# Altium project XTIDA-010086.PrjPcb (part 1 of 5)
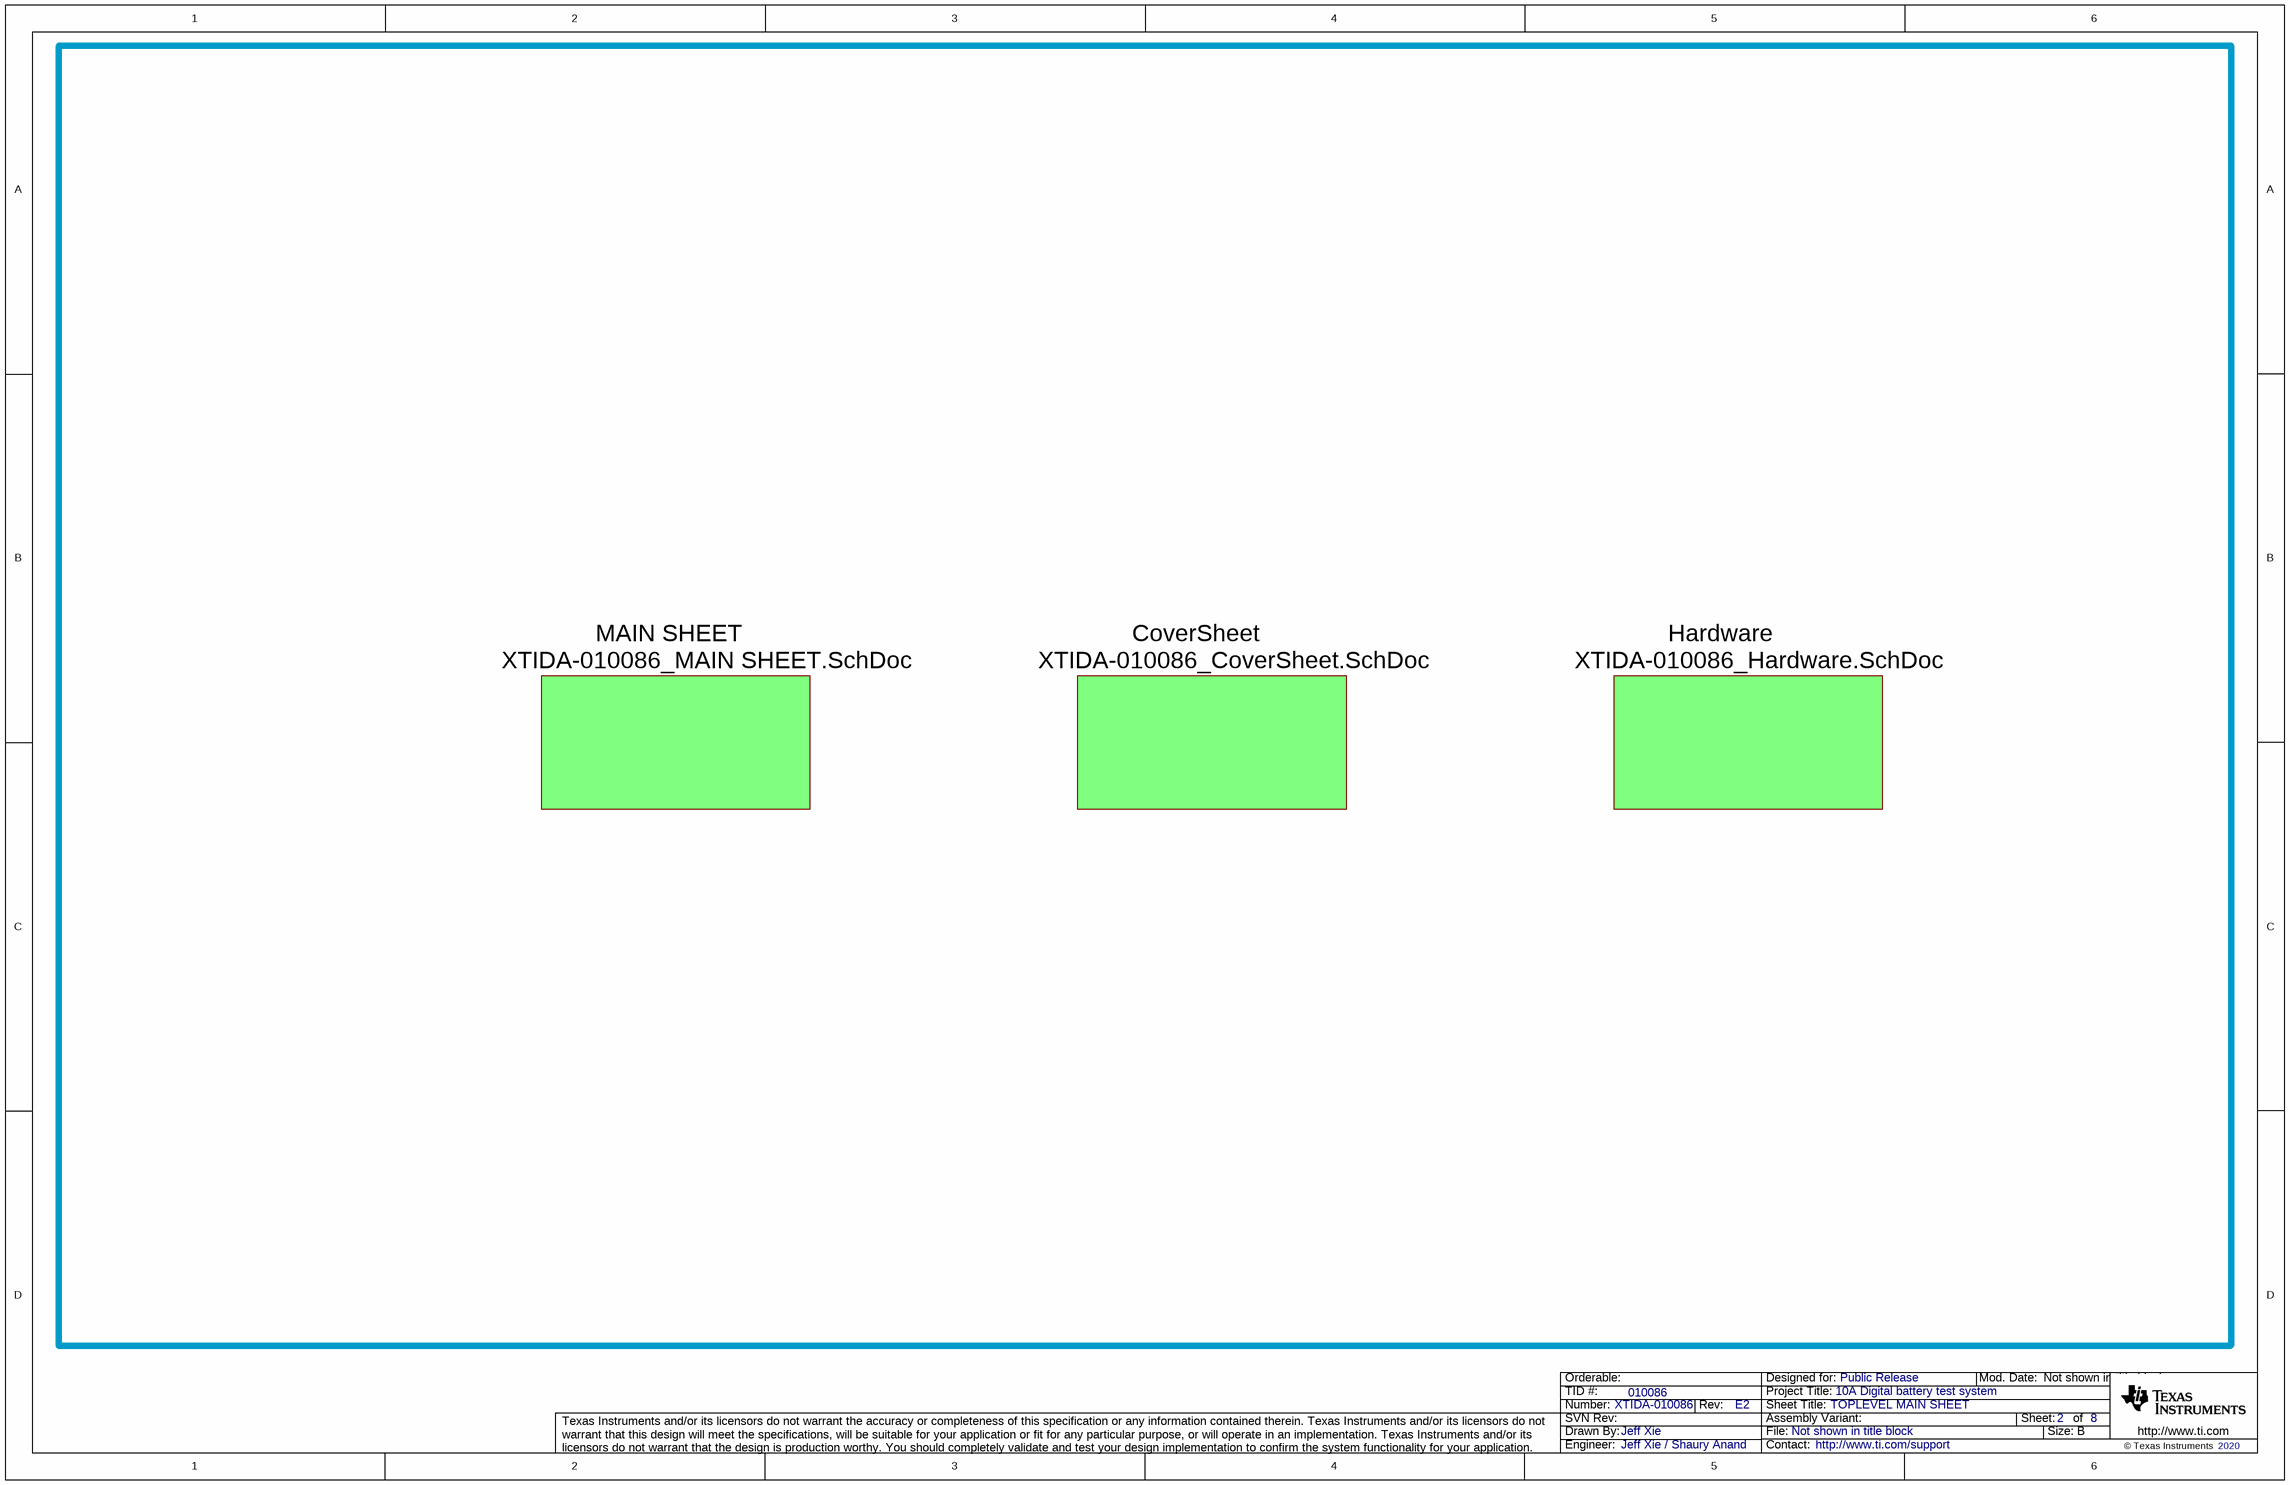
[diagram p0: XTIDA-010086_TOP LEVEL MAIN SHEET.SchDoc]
CopyrightYear: 2020; PCB_Layout: Avinash N; PCB_Rev: E2; PRJ_Customer: Public Release; PRJ_Engineer: Jeff Xie / Shaury Anand; PRJ_Number: XTIDA-010086; PRJ_Title: 10A Digital battery test system; SCH_Rev: E2; TechSupport: http://www.ti.com/support; TID: 010086
8 sheets, 1934 parts. Net scope: flat (ports and power ports of the same name join across sheets).
Board file: XTIDA-010086.PcbDoc
Sheets:
  XTIDA-010086_TOP LEVEL MAIN SHEET.SchDoc
    MAIN SHEET = XTIDA-010086_MAIN SHEET.SchDoc
      Ch1 = XTIDA-010086_Power Stage.SchDoc
      Ch2 = XTIDA-010086_Power Stage.SchDoc
      Ch3 = XTIDA-010086_Power Stage.SchDoc
      Ch4 = XTIDA-010086_Power Stage.SchDoc
      Ch5 = XTIDA-010086_Power Stage.SchDoc
      Ch6 = XTIDA-010086_Power Stage.SchDoc
      Ch7 = XTIDA-010086_Power Stage.SchDoc
      Ch8 = XTIDA-010086_Power Stage.SchDoc
      ADC = XTIDA-010086_ADC.SchDoc
      Bias Power Supply = XTIDA-010086_Bias Power Supply.SchDoc
      Control Card_28379 = XTIDA-010086_Control Card_28379.SchDoc
    CoverSheet = XTIDA-010086_CoverSheet.SchDoc
    Hardware = XTIDA-010086_Hardware.SchDoc

## Sheet XTIDA-010086_TOP LEVEL MAIN SHEET.SchDoc: TOPLEVEL MAIN SHEET
size 431 x 279 mm; Date: Not shown in title block; ApprovedBy: Not shown in title block; CheckedBy: Not shown in title block; Author: Not shown in title block; CompanyName: Not shown in title block; DrawnBy: Jeff Xie; Engineer: Not shown in title block; Organization: Not shown in title block; Address1: Not shown in title block; Address2: Not shown in title block; Address3: Not shown in title block; Address4: Not shown in title block; DocumentNumber: 1; Revision: Use project parameter SCH_Rev; SheetNumber: 2; SheetTotal: 8; PageSetup: Record=PageOptions¦CenterHorizontal=True¦CenterVertical=True¦PrintScale=1.00¦XCorrection=1.00¦YCorrection=1.00¦PrintKind=0¦BorderSize=5000000¦LeftOffset=0¦BottomOffset=0¦Orientation=2¦PaperLength=1000¦PaperWidth=1000¦Scale=100¦PaperSource=15¦PrintQuality=600¦MediaType=1¦DitherType=10¦PaperKind=Letter¦PrintScaleMode=1

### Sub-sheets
CoverSheet = XTIDA-010086_CoverSheet.SchDoc: no entries
Hardware = XTIDA-010086_Hardware.SchDoc: no entries
MAIN SHEET = XTIDA-010086_MAIN SHEET.SchDoc: no entries

## Sheet XTIDA-010086_MAIN SHEET.SchDoc: MAIN-Sheet
size 558 x 431 mm; Date: Not shown in title block; ApprovedBy: Not shown in title block; CheckedBy: Not shown in title block; Author: Not shown in title block; CompanyName: Not shown in title block; DrawnBy: Jeff Xie; Engineer: Not shown in title block; Organization: Not shown in title block; Address1: Not shown in title block; Address2: Not shown in title block; Address3: Not shown in title block; Address4: Not shown in title block; DocumentNumber: 1; Revision: Use project parameter SCH_Rev; SheetNumber: 3; SheetTotal: 8; PageSetup: Record=PageOptions¦CenterHorizontal=True¦CenterVertical=True¦PrintScale=1.00¦XCorrection=1.00¦YCorrection=1.00¦PrintKind=0¦BorderSize=5000000¦LeftOffset=0¦BottomOffset=0¦Orientation=2¦PaperLength=1000¦PaperWidth=1000¦Scale=100¦PaperSource=15¦PrintQuality=600¦MediaType=1¦DitherType=10¦PaperKind=Letter¦PrintScaleMode=1
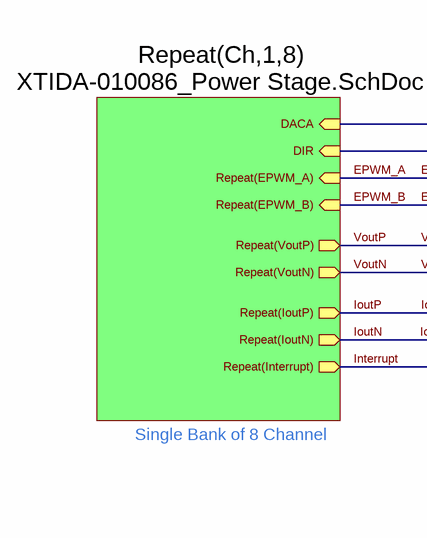
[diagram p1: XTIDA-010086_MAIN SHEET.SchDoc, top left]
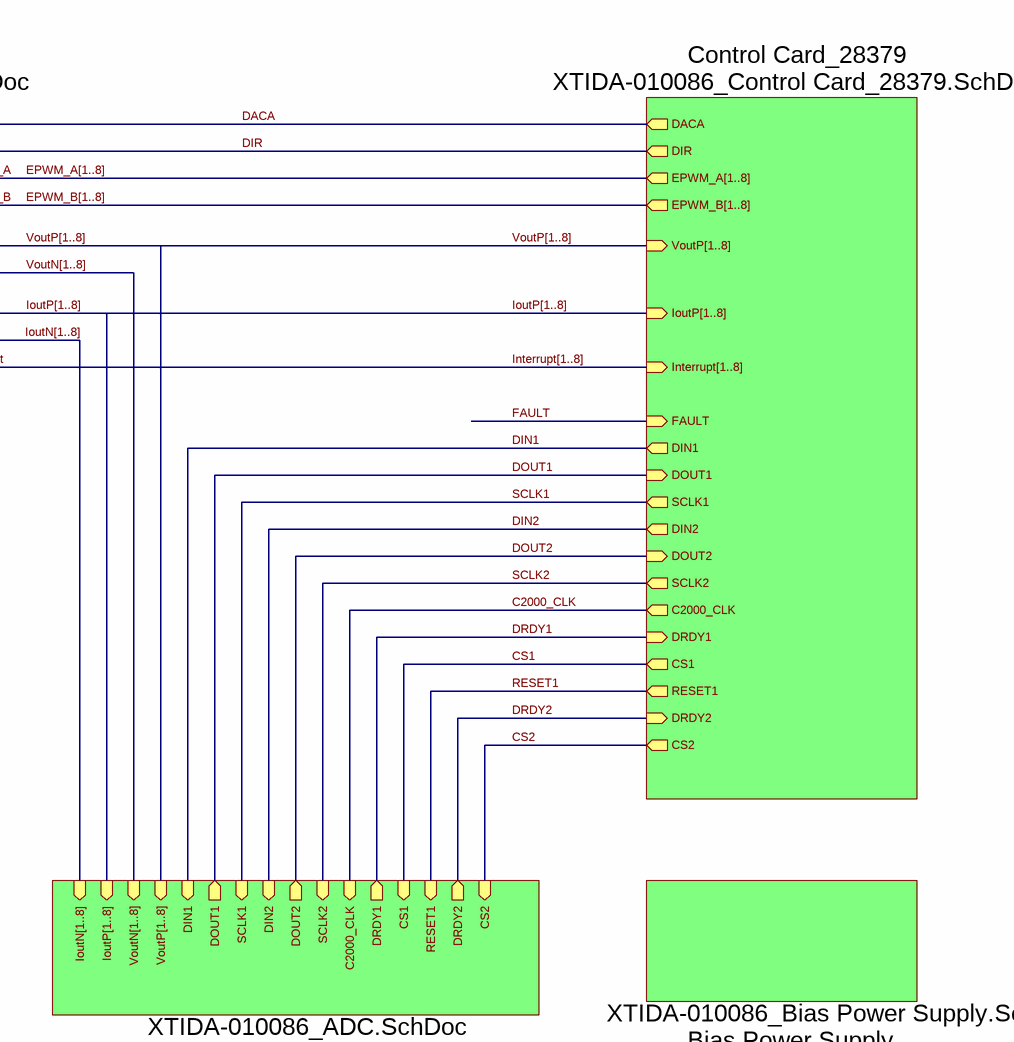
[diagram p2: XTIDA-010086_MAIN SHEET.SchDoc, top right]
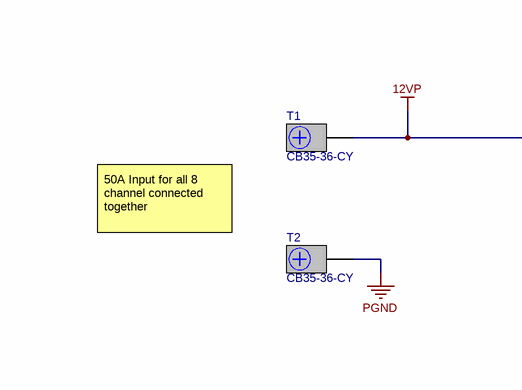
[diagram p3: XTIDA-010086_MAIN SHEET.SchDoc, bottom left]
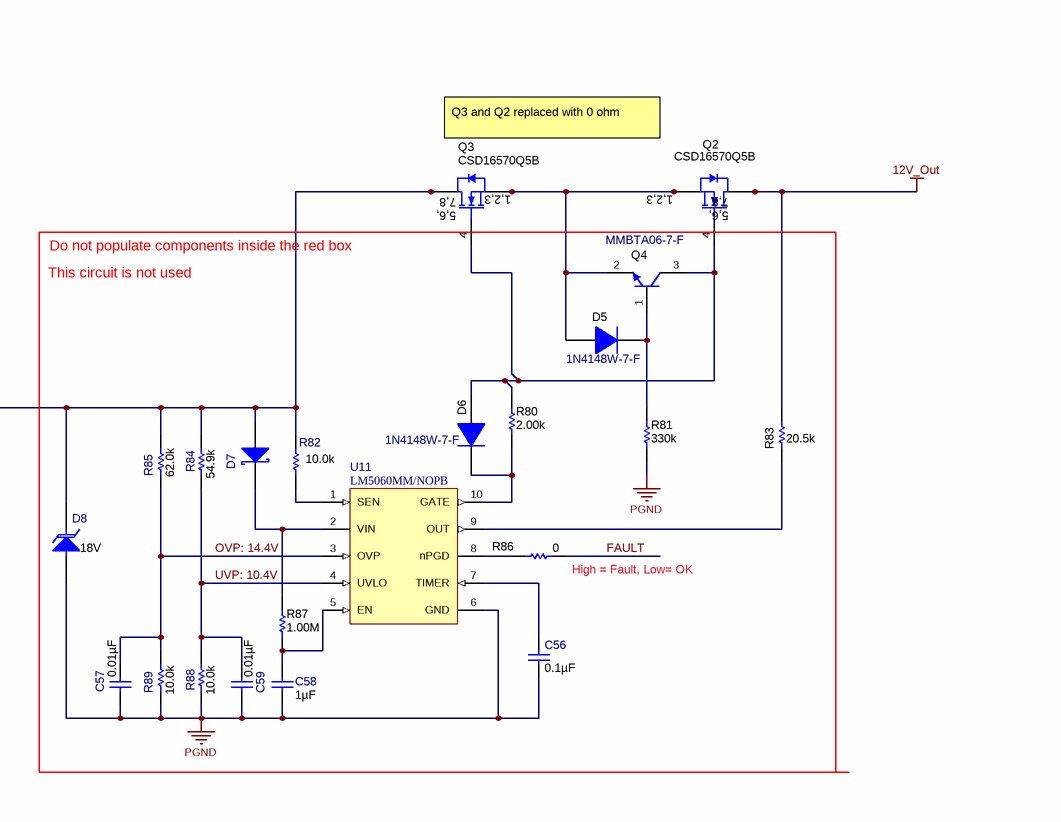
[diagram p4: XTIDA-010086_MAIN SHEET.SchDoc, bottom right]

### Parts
C56  ValueDisplayed: 0.1µF  [0603L]  (hidden comment: C0603C104J3RACTU)
C57  ValueDisplayed: 0.01µF  [0603L]  (hidden comment: GRM1885C1H103JA01D)
C58  ValueDisplayed: 1µF  [0603L]  (hidden comment: C0603C105K3RACTU)
C59  ValueDisplayed: 0.01µF  [0603L]  (hidden comment: GRM1885C1H103JA01D)
D5  1N4148W-7-F  [SOD-123]
D6  1N4148W-7-F  [SOD-123]
D7  NSR0240V2T1G  [SOD-523]  (value not drawn)
D8  value 18V  [SMA]  (hidden comment: SMAJ18A)
Q2  CSD16570Q5B  [DNK0008A]
Q3  CSD16570Q5B  [DNK0008A]
Q4  MMBTA06-7-F  [SOT-23]
R80  ValueDisplayed: 2.00k  [0603]  (hidden comment: CRCW06032K00FKEA)
R81  ValueDisplayed: 330k  [0603]  (hidden comment: RC0603FR-07330KL)
R82  ValueDisplayed: 10.0k  [0603L]  (hidden comment: RC0603FR-0710KL)
R83  ValueDisplayed: 20.5k  [0603]  (hidden comment: CRCW060320K5FKEA)
R84  ValueDisplayed: 54.9k  [0603L]  (hidden comment: RC0603FR-0754K9L)
R85  ValueDisplayed: 62.0k  [0603L]  (hidden comment: RC0603FR-0762KL)
R86  ValueDisplayed: 0  [0402]  (hidden comment: CRCW04020000Z0ED)
R87  ValueDisplayed: 1.00M  [0603]  (hidden comment: CRCW06031M00FKEA)
R88  ValueDisplayed: 10.0k  [0603L]  (hidden comment: RC0603FR-0710KL)
R89  ValueDisplayed: 10.0k  [0603L]  (hidden comment: RC0603FR-0710KL)
T1  CB35-36-CY  [CB35-36-CY]
T2  CB35-36-CY  [CB35-36-CY]
U11  LM5060MM/NOPB  [MUB10A_N]

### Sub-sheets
ADC = XTIDA-010086_ADC.SchDoc: VoutP[1..8] (in), IoutN[1..8] (in), IoutP[1..8] (in), VoutN[1..8] (in), DIN1 (in), DOUT1 (out), SCLK1 (in), DRDY1 (out), CS1 (in), RESET1 (in), SCLK2 (in), DIN2 (in), DOUT2 (out), DRDY2 (out), CS2 (in), C2000_CLK (in)
Bias Power Supply = XTIDA-010086_Bias Power Supply.SchDoc: no entries
Control Card_28379 = XTIDA-010086_Control Card_28379.SchDoc: SCLK1 (out), VoutP[1..8] (in), EPWM_A[1..8] (out), EPWM_B[1..8] (out), IoutP[1..8] (in), DIN2 (out), SCLK2 (out), DIN1 (out), DOUT1 (in), DOUT2 (in), C2000_CLK (out), DRDY1 (in), RESET1 (out), CS1 (out), DRDY2 (in), CS2 (out), FAULT (in), Interrupt[1..8] (in), DACA (out), DIR (out)
Repeat(Ch,1,8) = XTIDA-010086_Power Stage.SchDoc: Repeat(VoutP) (out), Repeat(IoutP) (out), Repeat(EPWM_A) (in), Repeat(EPWM_B) (in), Repeat(VoutN) (out), Repeat(IoutN) (out), DIR (in), Repeat(Interrupt) (out), DACA (in)

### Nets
12V_Out: Q2.5(D) Q2.6(D) Q2.7(D) Q2.8(D) Q2.9(D) R83.2
12VP: D7.2(A) D8.1(K) Q3.5(D) Q3.6(D) Q3.7(D) Q3.8(D) Q3.9(D) R82.1 R84.2 R85.2 T1.1
PGND: C56.1 C57.1 C58.2 C59.1 D8.2(A) R81.1 R88.1 R89.1 T2.1 U11.6(GND)
C2000_CLK: sheet ADC/C2000_CLK, sheet Control Card_28379/C2000_CLK
CS1: sheet ADC/CS1, sheet Control Card_28379/CS1
CS2: sheet ADC/CS2, sheet Control Card_28379/CS2
DACA: sheet Repeat(Ch,1,8)/DACA, sheet Control Card_28379/DACA
DIN1: sheet ADC/DIN1, sheet Control Card_28379/DIN1
DIN2: sheet ADC/DIN2, sheet Control Card_28379/DIN2
DIR: sheet Repeat(Ch,1,8)/DIR, sheet Control Card_28379/DIR
DOUT1: sheet ADC/DOUT1, sheet Control Card_28379/DOUT1
DOUT2: sheet ADC/DOUT2, sheet Control Card_28379/DOUT2
DRDY1: sheet ADC/DRDY1, sheet Control Card_28379/DRDY1
DRDY2: sheet ADC/DRDY2, sheet Control Card_28379/DRDY2
FAULT: R86.2 ; sheet Control Card_28379/FAULT
OVP: 14.4V: C57.2 R85.1 R89.2 U11.3(OVP)
RESET1: sheet ADC/RESET1, sheet Control Card_28379/RESET1
SCLK1: sheet ADC/SCLK1, sheet Control Card_28379/SCLK1
SCLK2: sheet ADC/SCLK2, sheet Control Card_28379/SCLK2
UVP: 10.4V: C59.2 R84.1 R88.2 U11.4(UVLO)
NetC56_2: C56.2 U11.7(TIMER)
NetC58_1: C58.1 R87.1 U11.5(EN)
NetD5_1: D5.1(K) Q4.1(B) R81.2
NetD5_2: D5.2(A) Q2.1(S) Q2.2(S) Q2.3(S) Q3.1(S) Q3.2(S) Q3.3(S) Q4.2(E)
NetD6_1: D6.1(K) R80.1 U11.10(GATE)
NetD6_2: D6.2(A) Q2.4(G) Q3.4(G) Q4.3(C) R80.2
NetD7_1: D7.1(K) R87.2 U11.2(VIN)
NetR82_2: R82.2 U11.1(SEN)
NetR83_1: R83.1 U11.9(OUT)
NetR86_1: R86.1 U11.8(nPGD)

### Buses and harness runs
bus EPWM_A[1..8] = sheet Control Card_28379/EPWM_A[1..8]
bus EPWM_B[1..8] = sheet Control Card_28379/EPWM_B[1..8]
bus Interrupt[1..8] = sheet Control Card_28379/Interrupt[1..8]
bus IoutN[1..8] = sheet ADC/IoutN[1..8]
bus IoutP[1..8] = sheet ADC/IoutP[1..8] = sheet Control Card_28379/IoutP[1..8]
bus VoutN[1..8] = sheet ADC/VoutN[1..8]
bus VoutP[1..8] = sheet ADC/VoutP[1..8] = sheet Control Card_28379/VoutP[1..8]

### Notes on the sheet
- Single Bank of 8 Channel
- Q3 and Q2 replaced with 0 ohm
- This circuit is not used
- Do not populate components inside the red box
- 50A Input for all 8 channel connected together
- (near R86) High = Fault, Low= OK

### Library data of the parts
C56 = C0603C104J3RACTU: CAP, CERM, 0.1 µF, 25 V, +/- 5%, X7R, 0603; Manufacturer: Kemet; Polarized: N; CompType: Capacitor; Value: 0.1uF; U/M: EA; Cap_F: 0.0000001; Tolerance_%: 5; Value1: Unknown; VDC_V: 25; Value2: 25V; TaMin_C: -55; TaMax_C: 125; Cap_Case: 0603; SizeArea_mm2: 1.28; SizeAreaWB_mm2: 4.68; SizeX_mm: 1.6; SizeY_mm: 0.8; SizeZ_mm: 1; AEC Category: Q200
C57 C59 = GRM1885C1H103JA01D: CAP, CERM, 0.01 µF, 50 V, +/- 5%, C0G/NP0, 0603; Manufacturer: MuRata; Polarized: N; CompType: Capacitor; Value: 0.01uF; U/M: EA; Cap_F: 0.00000001; Tolerance_%: 5; Value1: Unknown; VDC_V: 50; Value2: 50V; TaMin_C: -55; TaMax_C: 125; Cap_Case: 0603; SizeArea_mm2: 1.28; SizeAreaWB_mm2: 4.68; SizeX_mm: 1.6; SizeY_mm: 0.8; SizeZ_mm: 1; AEC Category: Q200
C58 = C0603C105K3RACTU: CAP, CERM, 1 µF, 25 V, +/- 10%, X7R, 0603; Manufacturer: Kemet; Polarized: N; CompType: Capacitor; Value: 1uF; U/M: EA; Cap_F: 0.000001; Tolerance_%: 10; Value1: Unknown; VDC_V: 25; Value2: 25V; TaMin_C: -55; TaMax_C: 125; Cap_Case: 0603; SizeArea_mm2: 1.28; SizeAreaWB_mm2: 4.68; SizeX_mm: 1.6; SizeY_mm: 0.8; SizeZ_mm: 1; AEC Category: Q200
D5 D6 = CMP-0029001-1: Diode, Ultrafast, 100 V, 0.15 A, SOD-123; Manufacturer: Diodes Inc.; Io_A: 150mA; Green_Lifecycle: Active; SizeAreaWB_mm2: 13.095; Vr_V: 100V; Green_REACh: Passed; Value1: 0.15A; TJmax_C: 150°C; U/M: EA; Value: 100V; SizeZ_mm: 1.35; SizeX_mm: 3.85; SizeY_mm: 1.7; Vf_V: 1.25V; SizeArea_mm2: 6.545; AEC Category: Q101
D7 = NSR0240V2T1G: Diode, Schottky, 40V, 0.25A, SOD-523; Manufacturer: ON Semiconductor; U/M: EA; Vf_V: 0.7; Value2: 0.7V; Io_A: 0.25; Vr_V: 40; TJmax_C: 150; RJC_CperW: 600
D8 = SMAJ18A: Diode, TVS, Uni, 18 V, 29.2 Vc, SMA; Manufacturer: Littelfuse; U/M: EA; Value1: 3.3W; Vr_V: 18; Power_W: 3.3; RJA_CperW: 120; AEC Category: Q101; AEC Qualified: N; SizeAreaWB_mm2: 37.3428; SizeArea_mm2: 16.3228; SizeX_mm: 5.59; SizeY_mm: 2.92; SizeZ_mm: 2.87
Q2 Q3 = CSD16570Q5B: MOSFET, N-CH, 25 V, 100 A, DNK0008A (VSON-CLIP-8); Manufacturer: Texas Instruments; Alternate Manufacturer: None; U/M: EA; ChType: N; Value: 25V; VdsMax_V: 25; Value1: 0.0008 ohm; Rdson45_ohm: 0.0008; Value2: 192 nC; QgTyp_nC: 192; Vgs_V: 20; IdsMax_A: 100; SizeAreaWB_mm2: 56; SizeArea_mm2: 30; SizeX_mm: 6; SizeY_mm: 5; SizeZ_mm: 1; AEC Category: Q101
Q4 = CMP-0000416-1: Transistor, NPN, 80 V, 0.5 A, SOT-23; Manufacturer: Diodes Inc.; TaMax_C: 150°C; Value1: 0.5 A; Vcesat1_V: 250mV; SizeX_mm: 2.5; SizeY_mm: 3; TaMin_C: -55°C; IcRated_A: 500mA; CompType: BJT; SizeZ_mm: 1.1; Value: 80 V; SizeArea_mm2: 7.5; NPN: 1; Vceo_V: 80V; PNP: 0; AEC Category: Q101; SizeAreaWB_mm2: 14; U/M: EA
R80 = CRCW06032K00FKEA: RES, 2.00 k, 1%, 0.1 W, 0603; Manufacturer: Vishay-Dale; CompType: Resistor; Value: 2.00k; Res_ohm: 2000; Value_Code: 2k00; Tolerance_%: 1; Power_W: 0.1; Value2: 0.1W; VDC_V: 75; TempCo: 100 ppm/C; SizeArea_mm2: 1.28; SizeX_mm: 1.6; SizeY_mm: 0.8; EIA_Code: E96; U/M: EA; AEC Category: Q200; Green_Lifecycle: Active; Green_REACh: Passed
R81 = RC0603FR-07330KL: RES, 330 k, 1%, 0.1 W, 0603; Manufacturer: Yageo America; CompType: Resistor; Value: 330k; Res_ohm: 330000; Tolerance_%: 1; Power_W: 0.1; Value2: 0.1W; VDC_V: 150; TempCo: 200 ppm/C; SizeArea_mm2: 1.28; SizeX_mm: 1.6; SizeY_mm: 0.8; U/M: EA; AEC Category: Q200; Green_Lifecycle: Active; Green_REACh: Passed
R82 R88 R89 = RC0603FR-0710KL: RES, 10.0 k, 1%, 0.1 W, 0603; Manufacturer: Yageo America; CompType: Resistor; Value: 10.0k; Res_ohm: 10000; Value_Code: 10k0; Tolerance_%: 1; Power_W: 0.1; Value2: 0.1W; VDC_V: 150; TempCo: 200 ppm/C; SizeArea_mm2: 1.28; SizeX_mm: 1.6; SizeY_mm: 0.8; EIA_Code: E96; U/M: EA; AEC Category: Q200
R83 = CRCW060320K5FKEA: RES, 20.5 k, 1%, 0.1 W, 0603; Manufacturer: Vishay-Dale; CompType: Resistor; Value: 20.5k; Res_ohm: 20500; Value_Code: 20k5; Tolerance_%: 1; Power_W: 0.1; Value2: 0.1W; VDC_V: 75; TempCo: 100 ppm/C; SizeArea_mm2: 1.28; SizeX_mm: 1.6; SizeY_mm: 0.8; EIA_Code: E96; U/M: EA; AEC Category: Q200; Green_Lifecycle: Active; Green_REACh: Passed
R84 = RC0603FR-0754K9L: RES, 54.9 k, 1%, 0.1 W, 0603; Manufacturer: Yageo America; CompType: Resistor; Value: 54.9k; Res_ohm: 54900; Value_Code: 54k9; Tolerance_%: 1; Power_W: 0.1; Value2: 0.1W; VDC_V: 150; TempCo: 200 ppm/C; SizeArea_mm2: 1.28; SizeX_mm: 1.6; SizeY_mm: 0.8; EIA_Code: E96; U/M: EA; AEC Category: Q200
R85 = RC0603FR-0762KL: RES, 62.0 k, 1%, 0.1 W, 0603; Manufacturer: Yageo America; CompType: Resistor; Value: 62.0k; Res_ohm: 62000; Value_Code: 62k0; Tolerance_%: 1; Power_W: 0.1; Value2: 0.1W; VDC_V: 150; TempCo: 200 ppm/C; SizeArea_mm2: 1.28; SizeX_mm: 1.6; SizeY_mm: 0.8; U/M: EA; AEC Category: Q200
R86 = CRCW04020000Z0ED: RES, 0, 5%, 0.063 W, 0402; Manufacturer: Vishay-Dale; CompType: Resistor; Value: 0; Value_Code: 0000; Tolerance_%: 5; Power_W: 0.063; Value2: 0.063W; VDC_V: 50; TempCo: 200 ppm/C; SizeArea_mm2: 0.5; SizeX_mm: 1; SizeZ_mm: 0.6; EIA_Code: E24; U/M: EA; AEC Category: Q200; Green_Lifecycle: Active; Green_REACh: Passed
R87 = CRCW06031M00FKEA: RES, 1.00 M, 1%, 0.1 W, 0603; Manufacturer: Vishay-Dale; CompType: Resistor; Value: 1.00Meg; Res_ohm: 1000000; Value_Code: 1M00; Tolerance_%: 1; Power_W: 0.1; Value2: 0.1W; VDC_V: 75; TempCo: 100 ppm/C; SizeArea_mm2: 1.28; SizeX_mm: 1.6; SizeY_mm: 0.8; EIA_Code: E96; U/M: EA; AEC Category: Q200; Green_Lifecycle: Active; Green_REACh: Passed
T1 T2 = CB35-36-CY: Terminal 50A Lug; Manufacturer: Panduit; SymbolCreator: crossc; CompType: Screw Terminal; ContactFinish: Copper; Voltage_V: 600; Cert_CULUS: Y; Green_Lifecycle: Not Set; Green_REACh: Incomplete
U11 = LM5060Q1MMX/NOPB: High-Side Protection Controller with Low Quiescent Current, 10-pin MSOP, Pb-Free; Manufacturer: Texas Instruments; CompType: Switcher; PackageTopMarking: ZXTT*SZAB; PowerWise: N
